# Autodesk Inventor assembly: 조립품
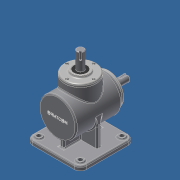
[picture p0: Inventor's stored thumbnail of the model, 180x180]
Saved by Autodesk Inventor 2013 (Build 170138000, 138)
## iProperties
Created: 2015-07
Part Number: 조립품
Document SubType Name: Assembly
Designer: Administrator
Author: Administrator
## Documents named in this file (14)
- C:\Users\Administrator\Desktop\450706V1012\조립품.iam
- C:\Users\Administrator\Desktop\450706V1012\본체.ipt
- C:\Users\Administrator\Desktop\450706V1012\서브 축.ipt
- 서브 축.ipt
- C:\Users\Administrator\Desktop\450706V1012\키 4x4.ipt
- C:\Users\Administrator\Desktop\450706V1012\서브 베벨기어.ipt
- C:\Users\Administrator\Desktop\450706V1012\커버.ipt
- C:\Users\Administrator\Desktop\450706V1012\베어링 6203.ipt
- C:\Users\Administrator\Desktop\450706V1012\오일실.ipt
- C:\Users\Administrator\Desktop\450706V1012\메인 축.ipt
- 메인 축.ipt
- C:\Users\Administrator\Desktop\450706V1012\키 5x5.ipt
- C:\Users\Administrator\Desktop\450706V1012\메인 베벨기어.ipt
- C:\Users\Administrator\Desktop\450706V1012\M4.ipt
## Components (8 placed, 1 different names)
1. M4:1
2. M4:2
3. M4:3
4. M4:4
5. M4:5
6. M4:6
7. M4:7
8. M4:8
